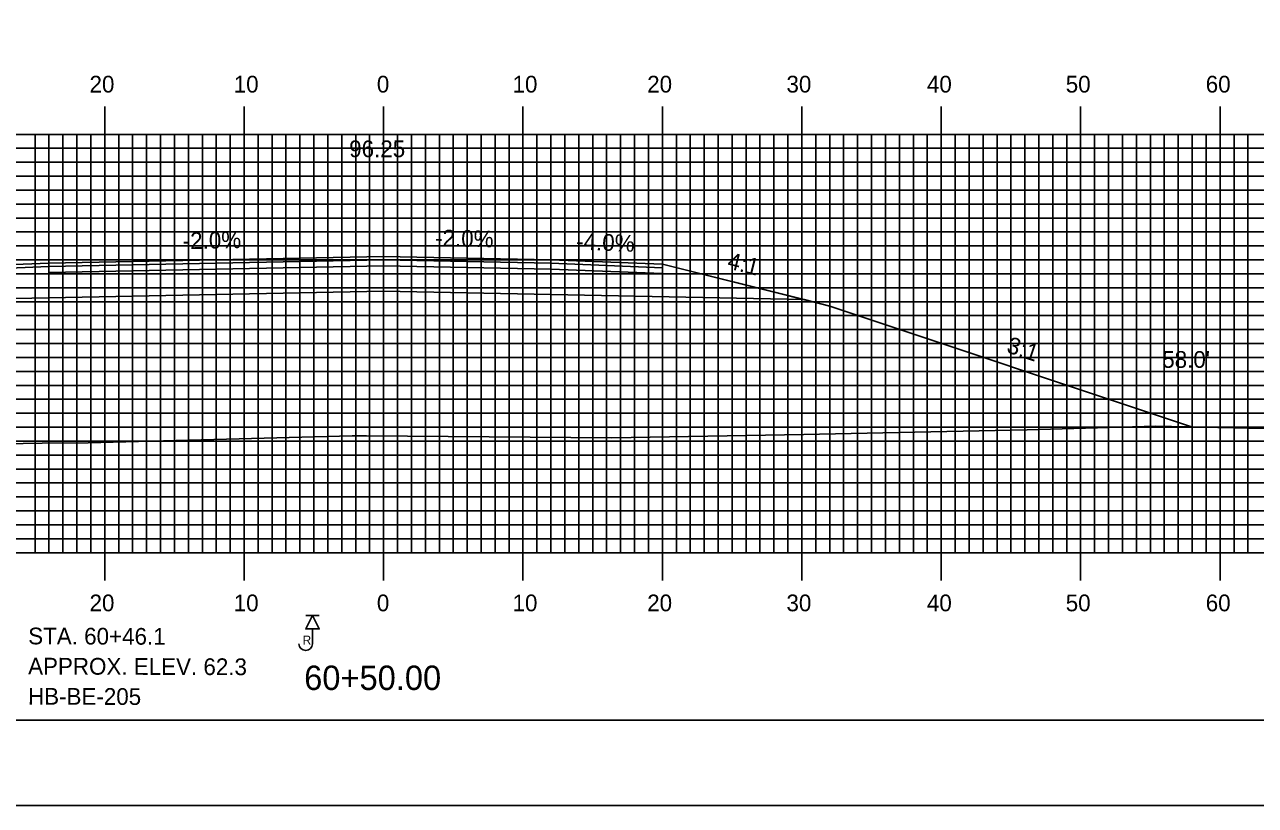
# Model space of a CAD drawing. Extents: x 1757856 to 1758199, y 442591 to 442811.
# Drawn here: x 1757995.9 to 1758084.2, y 442590.5 to 442646.5 of the extents above; entities that cross this region are included whole.
import ezdxf

# ---------------------------------------------------------------- set-up
doc = ezdxf.new("R2010")
doc.units = 0
for name, color, linetype in [('ANNOTATION', 7, 'Continuous'), ('BORDER', 7, 'Continuous'), ('BORING - REFUSAL', 7, 'Continuous'), ('D_Roadway_Centerline', 7, 'Continuous'), ('D_Roadway_Centerline_Text', 7, 'Continuous'), ('D_Roadway_Edge_Shoulder', 7, 'Continuous'), ('D_Roadway_Edge_TW', 7, 'Continuous'), ('D_Roadway_Pavement', 7, 'Continuous'), ('D_Roadway_SlopeLines', 7, 'Continuous'), ('D_Roadway_SubGrade', 7, 'Continuous'), ('D_Text_Standard', 7, 'Continuous'), ('H_V ANNOTATION', 7, 'Continuous'), ('MAJOR', 7, 'Continuous'), ('MINOR', 7, 'Continuous'), ('PLOT BOUNDARY', 7, 'Continuous'), ('S_Roadway_Centerline', 7, 'Continuous')]:
    doc.layers.add(name, color=color, linetype=linetype)

msp = doc.modelspace()

# ---------------------------------------------------------------- linework, layer by layer
at = {"layer": 'BORDER'}
msp.add_lwpolyline([(1757872.022, 442596.665), (1758192.022, 442596.665), (1758192.022, 442806.665), (1757872.022, 442806.665)], close=True, dxfattribs=at)
at = {"layer": 'BORING - REFUSAL'}
for p, q in [((1758017.002, 442604.157), (1758016.042, 442604.157)), ((1758016.522, 442603.197), (1758016.522, 442602.138))]:
    msp.add_line(p, q, dxfattribs=at)
msp.add_lwpolyline([(1758016.522, 442604.157), (1758017.002, 442603.197), (1758016.042, 442603.197)], close=True, dxfattribs=at)
msp.add_arc((1758016.037, 442602.138), 0.485, 180, 0, dxfattribs=at)
at = {"layer": 'D_Roadway_Centerline'}
msp.add_lwpolyline([(1757947.638, 442616.121), (1757977.622, 442626.116), (1757979.448, 442626.573), (1757989.622, 442629.116), (1757997.622, 442629.436), (1758009.622, 442629.676), (1758021.622, 442629.916), (1758033.622, 442629.676), (1758041.622, 442629.356), (1758051.796, 442626.813), (1758053.622, 442626.356), (1758079.651, 442617.68)], dxfattribs=at)
at = {"layer": 'D_Roadway_Edge_Shoulder'}
for points in [[(1757997.622, 442629.436), (1757989.622, 442629.116), (1757989.622, 442628.866), (1757997.622, 442629.186)], [(1758033.622, 442629.676), (1758041.622, 442629.356), (1758041.622, 442629.106), (1758033.622, 442629.426)]]:
    msp.add_lwpolyline(points, close=True, dxfattribs=at)
at = {"layer": 'D_Roadway_Edge_TW'}
for points in [[(1758009.622, 442629.426), (1758009.622, 442629.676), (1758021.622, 442629.916), (1758033.622, 442629.676), (1758033.622, 442629.426), (1758021.622, 442629.666)], [(1758009.622, 442629.676), (1757997.622, 442629.436), (1757997.622, 442629.186), (1758009.622, 442629.426)]]:
    msp.add_lwpolyline(points, close=True, dxfattribs=at)
msp.add_lwpolyline([(1758009.622, 442629.676), (1758009.622, 442629.426)], dxfattribs=at)
at = {"layer": 'D_Roadway_Pavement'}
for points in [[(1758009.622, 442629.426), (1757997.622, 442629.186), (1757997.622, 442628.769), (1758009.622, 442629.009)], [(1758009.622, 442629.009), (1758009.622, 442629.426), (1758021.622, 442629.666), (1758033.622, 442629.426), (1758033.622, 442629.009), (1758021.622, 442629.249)], [(1758033.622, 442629.426), (1758041.622, 442629.106), (1758041.622, 442628.689), (1758033.622, 442629.009)]]:
    msp.add_lwpolyline(points, close=True, dxfattribs=at)
for points in [[(1757997.622, 442629.186), (1757997.622, 442628.769)], [(1758009.622, 442629.426), (1758009.622, 442629.009)], [(1758009.622, 442629.426), (1758009.622, 442629.009)]]:
    msp.add_lwpolyline(points, dxfattribs=at)
at = {"layer": 'D_Roadway_SlopeLines'}
msp.add_lwpolyline([(1758041.622, 442629.356), (1758053.622, 442626.356), (1758079.651, 442617.68)], dxfattribs=at)
at = {"layer": 'D_Roadway_SubGrade'}
for points in [[(1757997.622, 442628.769), (1757997.622, 442629.186), (1757989.622, 442628.866), (1757989.622, 442629.116), (1757979.448, 442626.573), (1757997.622, 442626.936)], [(1758009.622, 442629.009), (1757997.622, 442628.769), (1757997.622, 442626.936), (1758009.622, 442627.176)], [(1758009.622, 442627.176), (1758009.622, 442629.009), (1758021.622, 442629.249), (1758033.622, 442629.009), (1758033.622, 442627.176), (1758021.622, 442627.416)], [(1758033.622, 442629.009), (1758041.622, 442628.689), (1758041.622, 442629.106), (1758041.622, 442629.356), (1758051.796, 442626.813), (1758033.622, 442627.176)]]:
    msp.add_lwpolyline(points, close=True, dxfattribs=at)
msp.add_lwpolyline([(1758009.622, 442629.009), (1758009.622, 442627.176)], dxfattribs=at)
at = {"layer": 'MAJOR'}
for p, q in [((1758001.622, 442640.669), (1758001.622, 442638.665)), ((1758011.622, 442640.669), (1758011.622, 442638.665)), ((1758021.622, 442640.669), (1758021.622, 442638.665)), ((1758031.622, 442640.669), (1758031.622, 442638.665)), ((1758041.622, 442640.669), (1758041.622, 442638.665)), ((1758051.622, 442640.669), (1758051.622, 442638.665)), ((1758061.622, 442640.669), (1758061.622, 442638.665)), ((1758071.622, 442640.669), (1758071.622, 442638.665)), ((1758081.622, 442640.669), (1758081.622, 442638.665)), ((1757881.622, 442638.665), (1758161.622, 442638.665)), ((1757881.622, 442638.665), (1758161.622, 442638.665)), ((1758001.622, 442608.665), (1758001.622, 442638.665)), ((1758011.622, 442608.665), (1758011.622, 442638.665)), ((1758021.622, 442608.665), (1758021.622, 442638.665)), ((1758031.622, 442608.665), (1758031.622, 442638.665)), ((1758041.622, 442608.665), (1758041.622, 442638.665)), ((1758051.622, 442608.665), (1758051.622, 442638.665)), ((1758061.622, 442608.665), (1758061.622, 442638.665)), ((1758071.622, 442608.665), (1758071.622, 442638.665)), ((1758081.622, 442608.665), (1758081.622, 442638.665)), ((1757881.622, 442633.665), (1758161.622, 442633.665)), ((1757881.622, 442628.665), (1758161.622, 442628.665)), ((1757881.622, 442623.665), (1758161.622, 442623.665)), ((1757881.622, 442618.665), (1758161.622, 442618.665)), ((1757881.622, 442613.665), (1758161.622, 442613.665)), ((1757881.622, 442608.665), (1758161.622, 442608.665)), ((1757881.622, 442608.665), (1758161.622, 442608.665)), ((1758001.622, 442606.661), (1758001.622, 442608.665)), ((1758011.622, 442606.661), (1758011.622, 442608.665)), ((1758021.622, 442606.661), (1758021.622, 442608.665)), ((1758031.622, 442606.661), (1758031.622, 442608.665)), ((1758041.622, 442606.661), (1758041.622, 442608.665)), ((1758051.622, 442606.661), (1758051.622, 442608.665)), ((1758061.622, 442606.661), (1758061.622, 442608.665)), ((1758071.622, 442606.661), (1758071.622, 442608.665)), ((1758081.622, 442606.661), (1758081.622, 442608.665))]:
    msp.add_line(p, q, dxfattribs=at)
at = {"layer": 'MINOR'}
for p, q in [((1757996.622, 442608.665), (1757996.622, 442638.665)), ((1757997.622, 442608.665), (1757997.622, 442638.665)), ((1757998.622, 442608.665), (1757998.622, 442638.665)), ((1757999.622, 442608.665), (1757999.622, 442638.665)), ((1758000.622, 442608.665), (1758000.622, 442638.665)), ((1758002.622, 442608.665), (1758002.622, 442638.665)), ((1758003.622, 442608.665), (1758003.622, 442638.665)), ((1758004.622, 442608.665), (1758004.622, 442638.665)), ((1758005.622, 442608.665), (1758005.622, 442638.665)), ((1758006.622, 442608.665), (1758006.622, 442638.665)), ((1758007.622, 442608.665), (1758007.622, 442638.665)), ((1758008.622, 442608.665), (1758008.622, 442638.665)), ((1758009.622, 442608.665), (1758009.622, 442638.665)), ((1758010.622, 442608.665), (1758010.622, 442638.665)), ((1758012.622, 442608.665), (1758012.622, 442638.665)), ((1758013.622, 442608.665), (1758013.622, 442638.665)), ((1758014.622, 442608.665), (1758014.622, 442638.665)), ((1758015.622, 442608.665), (1758015.622, 442638.665)), ((1758016.622, 442608.665), (1758016.622, 442638.665)), ((1758017.622, 442608.665), (1758017.622, 442638.665)), ((1758018.622, 442608.665), (1758018.622, 442638.665)), ((1758019.622, 442608.665), (1758019.622, 442638.665)), ((1758020.622, 442608.665), (1758020.622, 442638.665)), ((1758022.622, 442608.665), (1758022.622, 442638.665)), ((1758023.622, 442608.665), (1758023.622, 442638.665)), ((1758024.622, 442608.665), (1758024.622, 442638.665)), ((1758025.622, 442608.665), (1758025.622, 442638.665)), ((1758026.622, 442608.665), (1758026.622, 442638.665)), ((1758027.622, 442608.665), (1758027.622, 442638.665)), ((1758028.622, 442608.665), (1758028.622, 442638.665)), ((1758029.622, 442608.665), (1758029.622, 442638.665)), ((1758030.622, 442608.665), (1758030.622, 442638.665)), ((1758032.622, 442608.665), (1758032.622, 442638.665)), ((1758033.622, 442608.665), (1758033.622, 442638.665)), ((1758034.622, 442608.665), (1758034.622, 442638.665)), ((1758035.622, 442608.665), (1758035.622, 442638.665)), ((1758036.622, 442608.665), (1758036.622, 442638.665)), ((1758037.622, 442608.665), (1758037.622, 442638.665)), ((1758038.622, 442608.665), (1758038.622, 442638.665)), ((1758039.622, 442608.665), (1758039.622, 442638.665)), ((1758040.622, 442608.665), (1758040.622, 442638.665)), ((1758042.622, 442608.665), (1758042.622, 442638.665)), ((1758043.622, 442608.665), (1758043.622, 442638.665)), ((1758044.622, 442608.665), (1758044.622, 442638.665)), ((1758045.622, 442608.665), (1758045.622, 442638.665)), ((1758046.622, 442608.665), (1758046.622, 442638.665)), ((1758047.622, 442608.665), (1758047.622, 442638.665)), ((1758048.622, 442608.665), (1758048.622, 442638.665)), ((1758049.622, 442608.665), (1758049.622, 442638.665)), ((1758050.622, 442608.665), (1758050.622, 442638.665)), ((1758052.622, 442608.665), (1758052.622, 442638.665)), ((1758053.622, 442608.665), (1758053.622, 442638.665)), ((1758054.622, 442608.665), (1758054.622, 442638.665)), ((1758055.622, 442608.665), (1758055.622, 442638.665)), ((1758056.622, 442608.665), (1758056.622, 442638.665)), ((1758057.622, 442608.665), (1758057.622, 442638.665)), ((1758058.622, 442608.665), (1758058.622, 442638.665)), ((1758059.622, 442608.665), (1758059.622, 442638.665)), ((1758060.622, 442608.665), (1758060.622, 442638.665)), ((1758062.622, 442608.665), (1758062.622, 442638.665)), ((1758063.622, 442608.665), (1758063.622, 442638.665)), ((1758064.622, 442608.665), (1758064.622, 442638.665)), ((1758065.622, 442608.665), (1758065.622, 442638.665)), ((1758066.622, 442608.665), (1758066.622, 442638.665)), ((1758067.622, 442608.665), (1758067.622, 442638.665)), ((1758068.622, 442608.665), (1758068.622, 442638.665)), ((1758069.622, 442608.665), (1758069.622, 442638.665)), ((1758070.622, 442608.665), (1758070.622, 442638.665)), ((1758072.622, 442608.665), (1758072.622, 442638.665)), ((1758073.622, 442608.665), (1758073.622, 442638.665)), ((1758074.622, 442608.665), (1758074.622, 442638.665)), ((1758075.622, 442608.665), (1758075.622, 442638.665)), ((1758076.622, 442608.665), (1758076.622, 442638.665)), ((1758077.622, 442608.665), (1758077.622, 442638.665)), ((1758078.622, 442608.665), (1758078.622, 442638.665)), ((1758079.622, 442608.665), (1758079.622, 442638.665)), ((1758080.622, 442608.665), (1758080.622, 442638.665)), ((1758082.622, 442608.665), (1758082.622, 442638.665)), ((1758083.622, 442608.665), (1758083.622, 442638.665)), ((1757881.622, 442637.665), (1758161.622, 442637.665)), ((1757881.622, 442636.665), (1758161.622, 442636.665)), ((1757881.622, 442635.665), (1758161.622, 442635.665)), ((1757881.622, 442634.665), (1758161.622, 442634.665)), ((1757881.622, 442632.665), (1758161.622, 442632.665)), ((1757881.622, 442631.665), (1758161.622, 442631.665)), ((1757881.622, 442630.665), (1758161.622, 442630.665)), ((1757881.622, 442629.665), (1758161.622, 442629.665)), ((1757881.622, 442627.665), (1758161.622, 442627.665)), ((1757881.622, 442626.665), (1758161.622, 442626.665)), ((1757881.622, 442625.665), (1758161.622, 442625.665)), ((1757881.622, 442624.665), (1758161.622, 442624.665)), ((1757881.622, 442622.665), (1758161.622, 442622.665)), ((1757881.622, 442621.665), (1758161.622, 442621.665)), ((1757881.622, 442620.665), (1758161.622, 442620.665)), ((1757881.622, 442619.665), (1758161.622, 442619.665)), ((1757881.622, 442617.665), (1758161.622, 442617.665)), ((1757881.622, 442616.665), (1758161.622, 442616.665)), ((1757881.622, 442615.665), (1758161.622, 442615.665)), ((1757881.622, 442614.665), (1758161.622, 442614.665)), ((1757881.622, 442612.665), (1758161.622, 442612.665)), ((1757881.622, 442611.665), (1758161.622, 442611.665)), ((1757881.622, 442610.665), (1758161.622, 442610.665)), ((1757881.622, 442609.665), (1758161.622, 442609.665))]:
    msp.add_line(p, q, dxfattribs=at)
at = {"layer": 'PLOT BOUNDARY'}
msp.add_lwpolyline([(1757855.835, 442590.547), (1758195.835, 442590.547), (1758195.835, 442810.547), (1757855.835, 442810.547)], close=True, dxfattribs=at)
at = {"layer": 'S_Roadway_Centerline'}
msp.add_lwpolyline([(1757937.268, 442616.263), (1757943.122, 442616.076), (1757958.964, 442616.236), (1757961.105, 442616.305), (1757962.387, 442616.312), (1757966.829, 442616.303), (1757979.757, 442616.419), (1757983.596, 442616.32), (1757990.278, 442616.408), (1757997.128, 442616.512), (1758000.423, 442616.544), (1758019.361, 442617.042), (1758020.163, 442617.055), (1758020.395, 442617.058), (1758038.002, 442616.895), (1758051.766, 442617.144), (1758057.423, 442617.263), (1758067.774, 442617.472), (1758077.01, 442617.736), (1758084.807, 442617.569)], dxfattribs=at)

# ---------------------------------------------------------------- texts
at = {"layer": 'ANNOTATION'}
for s, rotation, p in [('-2.0%', 1.14576, (1758007.228, 442630.429)), ('-2.0%', 358.85424, (1758025.308, 442630.643)), ('-4.0%', 357.70939, (1758035.414, 442630.406)), ('4:1', 345.96376, (1758046.215, 442629.069)), ('3:1', 341.56522, (1758066.241, 442623.058))]:
    msp.add_text(s, height=1.2, rotation=rotation, dxfattribs=at).set_placement(p)
at = {"layer": 'BORING - REFUSAL'}
for s, p in [('STA. 60+46.1', (1757996.13, 442602.095)), ('APPROX. ELEV. 62.3', (1757996.123, 442599.935)), ('HB-BE-205', (1757996.116, 442597.775))]:
    msp.add_text(s, height=1.2, rotation=359.81416, dxfattribs=at).set_placement(p)
msp.add_text('R', height=0.64, dxfattribs=at).set_placement((1758015.813, 442602.082))
at = {"layer": 'D_Roadway_Centerline'}
for s, p in [('C', (1758021.617, 442629.916)), ('L', (1758021.622, 442629.909))]:
    msp.add_text(s, height=0.0146, dxfattribs=at).set_placement(p)
at = {"layer": 'D_Roadway_Centerline_Text'}
msp.add_text('96.25', height=1.2, dxfattribs=at).set_placement((1758019.155, 442637.029))
at = {"layer": 'D_Text_Standard'}
msp.add_text("58.0'", height=1.2, dxfattribs=at).set_placement((1758077.474, 442621.924))
at = {"layer": 'H_V ANNOTATION'}
for s, height, p in [('20', 1.2, (1758000.53, 442641.665)), ('10', 1.2, (1758010.873, 442641.665)), ('0', 1.2, (1758021.14, 442641.665)), ('10', 1.2, (1758030.873, 442641.665)), ('20', 1.2, (1758040.53, 442641.665)), ('30', 1.2, (1758050.52, 442641.665)), ('40', 1.2, (1758060.594, 442641.665)), ('50', 1.2, (1758070.552, 442641.665)), ('60', 1.2, (1758080.594, 442641.665)), ('20', 1.2, (1758000.53, 442604.465)), ('10', 1.2, (1758010.873, 442604.465)), ('0', 1.2, (1758021.14, 442604.465)), ('10', 1.2, (1758030.873, 442604.465)), ('20', 1.2, (1758040.53, 442604.465)), ('30', 1.2, (1758050.52, 442604.465)), ('40', 1.2, (1758060.594, 442604.465)), ('50', 1.2, (1758070.552, 442604.465)), ('60', 1.2, (1758080.594, 442604.465)), ('60+50.00', 1.75, (1758015.926, 442598.821))]:
    msp.add_text(s, height=height, dxfattribs=at).set_placement(p)

doc.saveas('drawing.dxf')
